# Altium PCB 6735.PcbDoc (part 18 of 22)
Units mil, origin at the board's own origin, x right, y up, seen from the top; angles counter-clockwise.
Board outline 2641.73 x 5165.35 mil, 6 copper layers (Top, Inner Layer 2, Inner Layer 3, Inner Layer 4, Inner Layer 5, Bottom), stack 35.7 mil thick; 1011 components, 790 nets, 4118 pads, 9325 vias.
Unrouted connection lines stored in the file: 4610.
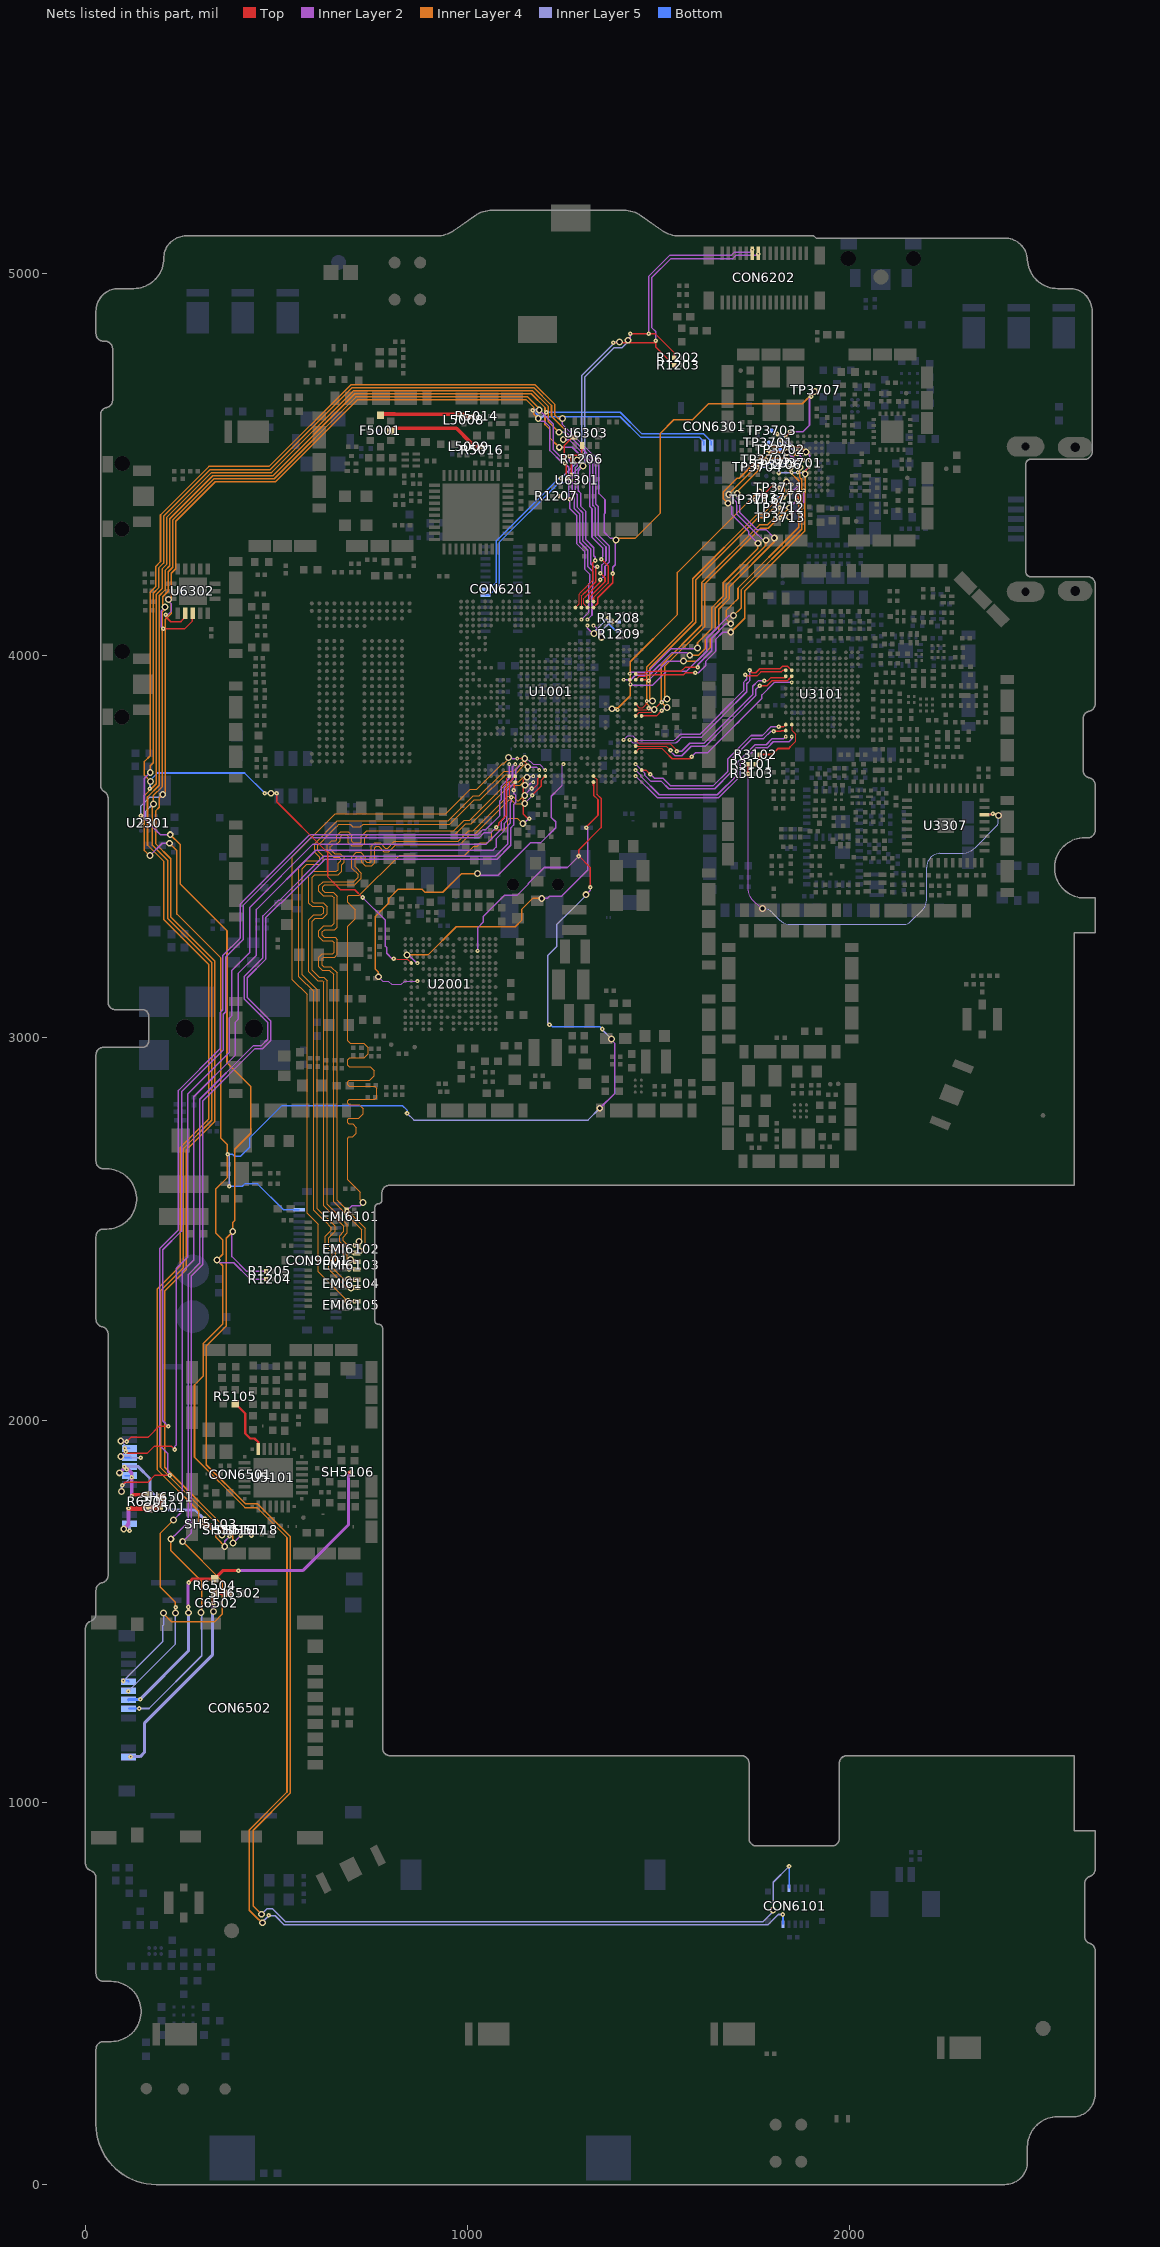
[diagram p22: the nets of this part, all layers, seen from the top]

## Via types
v1: diameter 12, hole 4, Top to Inner Layer 2, 3329 vias
v2: diameter 12, hole 4, Inner Layer 5 to Bottom, 3071 vias
v3: diameter 18, hole 10, Inner Layer 2 to Inner Layer 5, 1928 vias
v4: diameter 10, hole 4, Top to Inner Layer 2, 525 vias
v5: diameter 20, hole 12, Top to Bottom, 472 vias

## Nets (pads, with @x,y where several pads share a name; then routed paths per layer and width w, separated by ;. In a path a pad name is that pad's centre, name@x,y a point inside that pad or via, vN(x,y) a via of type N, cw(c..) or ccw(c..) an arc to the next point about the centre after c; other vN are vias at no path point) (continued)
RF_RX1_BBQP: U1001.AK6 U3101.M6 | length 513.1
  Top w3: U1001.AK6@1439.43,3748.01 1448.84,3757.43 1507.96,3757.43 1517.3,3748.09
  Top w4: 1517.3,3748.09 1535.3,3730.09 1581.31,3730.09 v1(1586.31,3735.09)
  Inner Layer 2 w4: v1(1586.31,3735.09) 1586.31,3737.09 1586.89,3737.09 1595.89,3746.09 1612.12,3746.09 1612.5,3746.48 1628.07,3746.48 1696.01,3814.41 1696.01,3814.49 1710.31,3828.78 1710.31,3829.27 1769.95,3888.91 1769.95,3895.79 1769.95,3897.21 1784.62,3911.88 1784.62,3912.2 1801.02,3928.6 1801.34,3928.6 1802.82,3930.09 v4(1847.91,3930.09)
RF_RX1_BBQP_C2K: TP3716.1 U1001.AG13 U3701.K9 | length 857.3
  Top w4: v1(1776.3,4409.11) 1776.3,4423.82 U3701.K9@1800.45,4447.97 U3701.K9@1800.57,4448.09 ; v4(1392.18,3858.25) 1393.14,3858.24 1392.3,3858.09 v4(1392.18,3858.25)
  Inner Layer 2 w4: v3(1377.44,3861.19) 1377.34,3862.05 1377.82,3861.57 1381.14,3858.24 v4(1392.18,3858.25) ; v3(1763.31,4428.09) 1763.31,4421.1 1775.8,4408.61 v1(1776.3,4409.11)
  Inner Layer 4 w4: v3(1377.44,3861.19) 1377.95,3863.83 1394.27,3863.83 1425.46,3895.02 1425.46,3984.37 1548.67,4107.58 1548.67,4217.79 1749.02,4418.15 1753.37,4418.15 v3(1763.31,4428.09)
  Inner Layer 5 w4: v2(1751.3,4408.09) 1763.31,4420.1 v3(1763.31,4428.09)
RF_RX2_BBIN: U1001.AK8 U3101.N5 | length 500.2
  Top w3: U1001.AK8@1439.43,3779.51 1449.5,3769.43 1530.23,3769.43 1547.31,3752.34 v1(1547.31,3750.09)
  Top w4: v1(1775.47,3934.13) 1784.63,3934.13 1793.37,3942.87 1829.21,3942.87 U3101.N5@1832.16,3945.83
  Inner Layer 2 w4: v1(1547.31,3750.09) 1560.22,3750.09 1581.16,3771.02 1618.68,3771.02 1672.01,3824.35 1672.01,3824.43 1686.31,3838.73 1686.31,3839.21 1745.94,3898.84 1745.94,3920.21 1759.87,3934.13 v1(1775.47,3934.13)
RF_RX2_BBIP: U1001.AK7 U3101.M5 | length 517.5
  Top w3: U1001.AK7@1439.43,3763.76 1439.42,3763.43 1519.55,3763.43 v1(1530.77,3752.21)
  Top w4: v1(1764.32,3921.61) 1783.43,3921.61 1796.69,3934.87 1837.09,3934.87 1840.17,3937.95 1840.17,3938.09 U3101.M5@1847.91,3945.83
  Inner Layer 2 w4: v1(1530.77,3752.21) 1529.5,3750.93 1542.34,3738.09 1560.12,3738.09 1584.99,3762.96 1621.93,3762.96 1680.01,3821.04 1680.01,3821.12 1694.31,3835.41 1694.31,3835.9 1753.95,3895.54 1753.95,3911.24 v1(1764.32,3921.61)
RF_RX2_BBQN: U1001.AH8 U3101.N4 | length 537.9
  Top w4: v1(1726.39,3949.77) 1726.88,3950.26 1729.93,3947.21 1756.79,3947.21 1767.28,3957.7 1820.17,3957.7 1824.05,3961.58 U3101.N4@1832.16,3961.58 ; v4(1407.93,3779.51) 1407.93,3779.71 v4(1407.93,3779.51)
  Inner Layer 2 w3: v4(1407.93,3779.51) 1419.25,3790.83 1431.56,3790.83 1443.87,3778.52 1539.75,3778.52 1542.96,3781.73 1543.93,3781.73 1545.8,3783.6
  Inner Layer 2 w4: 1545.8,3783.6 1557.29,3795.09 1608.81,3795.09 1648.01,3834.3 1648.01,3834.37 1662.31,3848.67 1662.31,3849.15 1721.83,3908.67 1721.83,3929.79 1721.94,3929.9 1721.94,3930.15 1730.39,3938.6 1730.39,3945.77 v1(1726.39,3949.77)
RF_RX2_BBQP: U1001.AJ8 U3101.M4 | length 549.4
  Top w4: v1(1738.11,3961.86) 1744.76,3955.21 1753.48,3955.21 1763.97,3965.7 1816.86,3965.7 1823.66,3972.5 1836.99,3972.5 U3101.M4@1847.91,3961.58
  Inner Layer 2 w3: v4(1423.68,3779.51) 1424,3779.82 1431.31,3772.52 1545.85,3772.52 1545.85,3773.09
  Inner Layer 2 w4: 1545.85,3773.09 1546.42,3773.66 1547.54,3773.66 1560.97,3787.09 1612.12,3787.09 1656.01,3830.98 1656.01,3831.06 1670.31,3845.35 1670.31,3845.84 1729.92,3905.45 1729.92,3926.57 ; 1729.94,3926.59 1729.94,3926.83 1738.39,3935.28 1738.39,3961.58 v1(1738.11,3961.86)
RF_TX_BBIN: U1001.AK3 U3101.N15 | length 505.3
  Top w3: v4(1439.43,3700.77) 1439.42,3700.96 v4(1439.43,3700.77)
  Top w4: U1001.AK3@1439.3,3700.76 v4(1439.43,3700.77) ; U1001.AK3@1439.3,3700.76 1439.3,3701.09 1439.75,3701.09 v4(1439.43,3700.77) ; U1001.AK3@1439.3,3700.76 v4(1439.43,3700.77)
  Inner Layer 2 w4: v4(1439.43,3700.77) 1453.31,3686.87 1453.31,3684.12 1501.34,3636.09 1653.04,3636.09 1705.65,3688.71 1705.65,3721.37 1751.45,3767.17 1780.92,3767.17 1796.37,3782.63 1826.44,3782.63 v4(1832.16,3788.35)
RF_TX_BBIN_C2K: TP3711.1 U1001.AK13 U3701.G9 | length 862.7
  Top w3: U1001.AK13@1439.43,3858.25 1439.58,3858.09 1468.31,3858.09 v1(1473.31,3863.09)
  Inner Layer 2 w4: v1(1473.31,3863.09) 1477.31,3859.09 v3(1488.31,3859.09) ; v3(1834.31,4455.09) 1840.81,4455.09 1847.81,4448.09 v4(1847.69,4447.97)
  Inner Layer 4 w4: v3(1488.31,3859.09) 1484.1,3859.09 1468.31,3874.88 1468.31,3970.48 1588.67,4090.83 1588.67,4201.23 1757.08,4369.64 1771.33,4369.64 1827.94,4426.25 1827.94,4448.72 v3(1834.31,4455.09)
  Inner Layer 5 w4: v2(1815.49,4439.1) 1816.19,4438.39 1833.59,4455.79 v3(1834.31,4455.09)
  Bottom w4: TP3711.1@1815.3,4439.09 v2(1815.49,4439.1)
RF_TX_BBIP: U1001.AK2 U3101.M15 | length 521.5
  Inner Layer 2 w4: v4(1439.43,3685.02) 1496.35,3628.09 1656.43,3628.09 1713.65,3685.31 1713.65,3718.06 1754.76,3759.17 1784.23,3759.17 1799.69,3774.63 1840.69,3774.63 1847.91,3781.85 v4(1847.91,3788.35)
RF_TX_BBIP_C2K: TP3710.1 U1001.AK14 U3701.F9 | length 841.8
  Top w3: U1001.AK14@1439.43,3873.99 1449.33,3864.09 1458.59,3864.09 1467.53,3873.03 1467.53,3881.09 v4(1468.31,3881.09)
  Inner Layer 2 w4: v4(1468.31,3881.09) v3(1483.31,3881.09) ; v3(1843.31,4429.09) 1849.3,4429.09 1864.3,4444.09 1864.3,4447.11 v4(1863.44,4447.97)
  Inner Layer 4 w4: v3(1483.31,3881.09) 1476.31,3888.09 1476.31,3967.14 1596.67,4087.49 1596.67,4197.91 1759.62,4360.87 1775.09,4360.87 v3(1843.31,4429.09)
  Inner Layer 5 w4: v2(1827.31,4413.09) 1837.3,4423.07 v3(1843.31,4429.09)
  Bottom w4: TP3710.1@1812.31,4412.09 1812.31,4412.59 1827.31,4412.59 v2(1827.31,4413.09)
RF_TX_BBQN: U1001.AK4 U3101.N14 | length 506
  Top w4: v1(1800.92,3802.63) 1800.92,3801.75 1819.01,3801.75 1821.36,3804.1 U3101.N14@1832.16,3804.1
  Inner Layer 2 w4: v4(1439.43,3716.51) 1462.95,3692.98 1462.95,3687.66 1479.53,3671.09 1507.07,3671.09 1526.07,3652.09 1646.33,3652.09 1688.29,3694.05 1688.29,3726.64 1744.82,3783.17 1756.13,3783.17 1756.19,3783.24 1774.34,3783.24 1793.72,3802.63 v1(1800.92,3802.63) v1@1801.14,3802.63
RF_TX_BBQN_C2K: TP3713.1 U1001.AK12 U3701.E10 | length 855.7
  Top w3: U1001.AK12@1439.43,3842.5 1449.01,3852.09 1480.31,3852.09 1506.31,3878.09 v1(1508.31,3878.09)
  Inner Layer 2 w4: v1(1508.31,3878.09) 1517.31,3887.09 v3(1521.31,3887.09) ; v3(1842.31,4363.09) 1878.97,4399.74 1878.97,4432.22 v4(1879.19,4432.22)
  Inner Layer 4 w4: v3(1521.31,3887.09) 1515.31,3893.09 1515.31,3971.99 1620.67,4077.34 1620.67,4187.97 1766.17,4333.47 1786.55,4333.47 1820.78,4367.7 1837.7,4367.7 v3(1842.31,4363.09)
  Inner Layer 5 w4: v2(1817.3,4361.09) 1840.31,4361.09 v3(1842.31,4363.09)
RF_TX_BBQP: U1001.AL3 U3101.N13 | length 480.3
  Top w4: U1001.AL3@1455.17,3700.77 1466.82,3700.76 v1(1477.85,3689.73) ; v1(1813.76,3813.75) 1826.07,3813.75 U3101.N13@1832.16,3819.85
  Inner Layer 2 w4: v1(1477.85,3689.73) 1488.5,3679.09 1510.96,3679.09 1529.96,3660.09 1643.01,3660.09 1680.29,3697.37 1680.29,3729.95 1741.58,3791.24 1771.02,3791.24 1794.41,3814.63 1813.76,3814.63 v1(1813.76,3813.75)
RF_TX_BBQP_C2K: TP3712.1 U1001.AL12 U3701.F10 | length 844
  Top w4: U1001.AL12@1455.17,3842.5 1493.72,3842.49 v1(1507.31,3856.09) ; v1(1860.31,4407.09) 1863.44,4410.21 U3701.F10@1863.44,4432.22
  Inner Layer 2 w4: v1(1507.31,3856.09) 1515.31,3864.09 v3(1521.31,3864.09) ; v3(1842.31,4387.09) 1841.81,4387.59 1860.81,4406.59 v1(1860.31,4407.09)
  Inner Layer 4 w4: v3(1521.31,3864.09) 1506.31,3879.09 1506.31,3974.37 1612.67,4080.73 1612.67,4191.28 1763.5,4342.12 1783.89,4342.12 1817.63,4375.86 1831.09,4375.86 v3(1842.31,4387.09)
  Inner Layer 5 w4: v2(1816.3,4387.09) v3(1842.31,4387.09)
RF_TXDET: R3101.2 R3103.1 U3307.17 | length 1256.5
  Top w5: R3101.2@1733.65,3716.09 R3103.1@1733.65,3691.09 1734.52,3691.09 v1(1734.6,3691.01) ; U3307.17@2352.03,3583.94 2352.03,3585.04 2374.38,3585.04 v1(2374.38,3586.4)
  Inner Layer 2 w3: v1(1734.6,3691.01) 1734.15,3690.57 1734.15,3385.59 ccw(c1767,3385.59) 1743.77,3362.36 1767.55,3338.59 v3(1771.65,3338.59) ; v1(2374.38,3586.4) 2377.73,3586.4 cw(c2377.73,3571.65) 2388.16,3582.08 v3(2388.65,3581.59)
  Inner Layer 5 w3: v3(1771.65,3338.59) 1772.65,3338.59 cw(c1772.65,3306.52) 1795.33,3329.2 1814.82,3309.71 ccw(c1845.28,3340.18) 1845.28,3297.09 2142.75,3297.09 ccw(c2142.75,3319.48) 2158.58,3303.65 2190.85,3335.91 ccw(c2167.17,3359.59) 2200.65,3359.59 2200.65,3446.66 cw(c2234.21,3446.66) 2210.48,3470.39 2213.51,3473.42 cw(c2235.65,3451.28) 2235.65,3482.59 2289.65,3482.59 ccw(c2289.65,3537.8) 2328.69,3498.76 2382.19,3552.26 ccw(c2366.6,3567.85) 2388.65,3567.85 v3(2388.65,3581.59)
RF_TXDET_MT6169: R3101.1 R3102.1 U3101.M13 | length 187.4
  Top w3: 1843.99,3761.25 1843.65,3761.59 1858.3,3776.24 1858.3,3781.56 1858.41,3781.67 1858.41,3793.84 1847.91,3804.34 U3101.M13@1847.91,3819.85
  Top w5: R3101.1@1753.65,3716.09 1755.67,3718.1 ccw(c1735.18,3738.59) 1764.15,3738.59 R3102.1@1764.15,3741.09 ; R3102.1@1762.66,3741.99 1763.25,3741.99 R3102.1@1764.15,3741.09 ; 1839.12,3757.06 1811.72,3757.06 1795.75,3741.09 R3102.1@1764.15,3741.09 ; 1839.16,3757.09 1839.83,3757.09 1843.99,3761.25
RF_WBT: F5001.8 L5008.1 R5014.1 | length 250.8
  Top w10: F5001.8@771.95,4629.45 771.95,4632.09 797.19,4632.09 797.31,4631.97 808.89,4631.97 ; 808.92,4631.94 809.16,4631.94 ; 809.18,4631.92 809.35,4631.92 ; 809.37,4631.9 809.53,4631.9 809.81,4631.87 809.85,4631.83 990.31,4631.83 L5008.1@990.31,4626.09 R5014.1@1014.31,4626.09
RF_WF_5G: F5001.6 L5009.1 R5016.1 | length 267.2
  Top w10: F5001.6@798.53,4588.11 805.51,4595.09 970.32,4595.09 1006.31,4559.1 1006.49,4559.1 1012.31,4553.28 L5009.1@1012.31,4547.09 ; L5009.1@1012.31,4546.09 L5009.1@1012.31,4547.09 ; R5016.1@1038.31,4547.09 L5009.1@1012.31,4547.09
RFIC1_BSI_CK: TP3703.1 U1001.AJ19 U3701.D5 | length 1121.4
  Inner Layer 2 w4: v4(1423.68,3952.73) 1427.54,3956.6 1470.4,3956.6 1531.89,4018.09 1596.31,4018.09 v3(1601.31,4020.09) ; v3(1681.31,4398.83) 1691.31,4388.83 1691.31,4368.86 1735.74,4324.43 1735.74,4317.66 v3(1759.31,4294.09) ; v3(1885.31,4533.09) 1894.94,4523.46 v4(1894.93,4510.96)
  Inner Layer 4 w4: v3(1601.31,4020.09) 1601.31,4034.12 1638.95,4071.76 1638.95,4126.3 1668.95,4156.3 1668.95,4190.92 1759.31,4281.29 v3(1759.31,4294.09) ; v3(1681.31,4398.83) 1668.22,4411.92 1668.22,4427.7 1704.61,4464.09 1710.71,4464.09 1793.71,4547.09 1871.31,4547.09 v3(1885.31,4533.09)
  Inner Layer 5 w4: v2(1810.05,4580.13) 1820.31,4580.13 1854.36,4546.09 1870.3,4546.09 v3@1879.3,4537.09
  Bottom w4: TP3703.1@1795.31,4589.09 1797.12,4590.89 1807.89,4580.13 v2(1810.05,4580.13)
RFIC1_BSI_D0: TP3702.1 U1001.AL18 U3701.E5 | length 1066.5
  Top w4: U1001.AL18@1455.17,3936.99 1473.75,3936.99 1474.55,3937.78 1474.69,3937.64 v1(1474.22,3934.97)
  Inner Layer 2 w4: v1(1474.22,3934.97) 1474.22,3936.55 1523.48,3985.81 1545.69,3985.81 1545.97,3986.09 v3(1564.31,3986.09) ; v3(1705.31,4424.09) 1705.31,4412.09 1712.31,4405.09 1712.31,4373.91 1756.13,4330.09 1780.31,4330.09 v3(1802.31,4308.09) ; v3@1868.31,4530.09 v3(1862.31,4531.09) 1879.97,4513.43 1879.97,4511.74 v4(1879.19,4510.96)
  Inner Layer 4 w4: v3(1564.31,3986.09) 1587.69,3986.09 1587.95,3985.83 1599.58,3985.83 1634.95,4021.2 1634.95,4041.89 1656.95,4063.89 1656.95,4121.67 1684.95,4149.67 1684.95,4180.58 1802.31,4297.94 v3(1802.31,4308.09) ; v3(1705.31,4424.09) 1704.78,4424.09 1704.78,4429.09 1792.78,4517.09 1848.31,4517.09 v3(1862.31,4531.09)
  Inner Layer 5 w4: v2(1820.32,4563.15) 1825.72,4563.15 1836.58,4552.29 1857.79,4531.09 v3(1862.31,4531.09)
  Bottom w4: TP3702.1@1817.31,4539.09 1817.31,4560.15 v2(1820.32,4563.15)
RFIC1_BSI_EN: TP3701.1 U1001.AH18 U3701.F5 | length 1071.9
  Inner Layer 2 w4: v4(1407.93,3936.99) 1426.71,3936.98 1438.32,3948.59 1474.95,3948.59 1533.58,4007.22 1575.05,4007.22 v3(1581.12,4001.15) ; v3(1683.22,4421.49) 1703.95,4400.76 1703.95,4370.96 1759.23,4315.68 1759.73,4315.68 1771.31,4304.09 v3(1780.31,4302.09) ; v3(1835.31,4532.09) 1847.31,4520.09 1852.1,4520.09 1862.33,4509.85 v4(1863.44,4510.96)
  Inner Layer 4 w4: v3(1581.12,4001.15) 1603.59,4001.15 1621.95,4019.51 1621.95,4042.23 1647.95,4068.23 1647.95,4123.99 1676.95,4152.99 1676.95,4185.78 1780.31,4289.15 v3(1780.31,4302.09) ; v3(1683.22,4421.49) 1682.36,4422.35 1792.1,4532.09 v3(1835.31,4532.09)
  Inner Layer 5 w4: v2(1788.31,4536.09) 1831.31,4536.09 v3(1835.31,4532.09)
  Bottom w4: v2(1788.31,4536.09) 1788.31,4546.09 TP3701.1@1788.3,4557.09
RFIC1_TX_BSI_CK: TP3706.1 U1001.AK18 U3701.E7 | length 957.5
  Top w3: U1001.AK18@1439.43,3936.99 1449.05,3946.61 1465.15,3946.61 1468.63,3950.09 1489.3,3950.09
  Top w4: 1489.3,3950.09 1565.04,3950.09 1570.11,3955.16 v1(1595.79,3955.16) ; U3701.E7@1879.19,4479.47 1879.06,4479.59 1893.43,4493.96 v4(1893.3,4494.09)
  Inner Layer 2 w4: v1(1595.79,3955.16) 1604.02,3955.16 1622.44,3973.58 1622.44,3984.83 1648.7,4011.09 1648.7,4042.69 1667.54,4061.53 v3(1688.16,4061.53) ; v3(1883.3,4475.09) 1883.3,4484.09 v4(1893.3,4494.09)
  Inner Layer 4 w4: v3(1688.16,4061.53) 1724.88,4098.25 1724.88,4169.27 1882.31,4326.71 1882.31,4425.82 1883.3,4426.81 v3(1883.3,4475.09)
  Inner Layer 5 w4: v2(1814.31,4478.09) 1880.3,4478.09 v3(1883.3,4475.09)
  Bottom w4: TP3706.1@1810.3,4500.09 1814.31,4496.07 v2(1814.31,4478.09)
RFIC1_TX_BSI_D0: TP3705.1 U1001.AJ18 U3701.F7 | length 963.8
  Top w4: U1001.AJ18@1423.68,3936.99 1424.84,3936.99 1424.84,3925.06 v4(1426,3925.06)
  Inner Layer 2 w4: v4(1426,3925.06) 1428.46,3922.61 1483.66,3922.61 1520.15,3959.09 1572.84,3959.09 1625.38,4011.63 1625.38,4045.95 1683.35,4103.92 1683.35,4104.23 1683.74,4104.62 1695.82,4104.62 v3(1695.82,4104.94) ; v4(1863.44,4479.47) 1863.44,4486.23 v3(1870.3,4493.09)
  Inner Layer 4 w4: v3(1695.82,4104.94) 1715.31,4124.43 1715.31,4172.13 1874.31,4331.13 1874.31,4461.79 1868.3,4467.81 1868.3,4479.07 1868.31,4493.09 v3(1870.3,4493.09)
  Inner Layer 5 w4: v2(1781.31,4512.09) 1781.31,4514.09 1815.27,4514.09 1820.27,4509.09 1851.41,4509.09 1867.41,4493.09 v3(1870.3,4493.09)
RFIC1_TX_BSI_EN: TP3704.1 U1001.AK19 U3701.G7 | length 942.9
  Top w3: U1001.AK19@1439.43,3952.73 1462.79,3952.73 1469.14,3959.09 1489.3,3959.09
  Top w4: 1489.3,3959.09 1558.42,3959.09 1569.57,3970.24 v1(1602.13,3970.24)
  Inner Layer 2 w4: v1(1602.13,3970.24) 1602.13,3976.48 1638.31,4012.66 1638.31,4045.77 1676.07,4083.53 v3(1688.16,4083.53) ; v3(1844.31,4494.09) 1846,4494.09 1846,4479.46 v4(1847.69,4479.47)
  Inner Layer 4 w4: v3(1688.16,4083.53) 1675.95,4095.73 1675.95,4118.04 1684.74,4126.83 1695.74,4137.83 1703.95,4146.05 1707.31,4149.41 1707.31,4176.93 1866.31,4335.93 1866.31,4457.44 1844.31,4479.44 v3(1844.31,4494.09)
  Inner Layer 5 w4: v2(1759.3,4493.09) 1780.19,4493.09 1793.19,4506.09 1808.65,4506.09 1815.65,4499.09 1839.31,4499.09 v3(1844.31,4494.09)
RTC32K1V8: U1001.AC1 U2001.P5 | length 868.4
  Top w4: v1(1309.73,3549.88) 1308.95,3550.83 1340.95,3582.83 1340.95,3623.52 1329.95,3634.52 1329.95,3658.93 1329.19,3659.69 U1001.AC1@1329.19,3669.27
  Inner Layer 2 w4: v3(841.27,3217.06) 845.61,3217.06 866.72,3195.95 v4(868.34,3195.95) ; v3(1193.95,3364.83) 1207.95,3364.83 1213.95,3370.83 1245.67,3370.83 1313.95,3439.11 1313.95,3546.58 1310.19,3550.34 v1(1309.73,3549.88)
  Inner Layer 4 w4: v3(841.27,3217.06) 896.48,3217.06 970.25,3290.83 1124.27,3290.83 1141.95,3308.52 1141.95,3337.04 1169.74,3364.83 v3(1193.95,3364.83)
RXIN_P: R5105.1 U5101.23 | length 152.7
  Top w4: R5105.1@391.29,2042.07 R5105.1@392.31,2043.09 R5105.1@393.31,2043.09
  Top w6: R5105.1@392.31,2043.09 418.31,2017.09 418.31,1965.19 431.42,1952.09 442.48,1952.09 451.93,1942.64 U5101.23@451.93,1923.99
SCL0: CON6201.23 CON6202.18 R1203.2 U1001.AA30 | length 1932.6
  Top w3: U1001.AA30@1297.69,4125.96 1297.69,4156.23 1301.95,4160.49
  Top w4: 1301.95,4160.49 1307.7,4166.23 1307.95,4166.23 1334.95,4193.23 1334.95,4227.83 1338.95,4231.83 v1(1339.15,4232.93) ; v1(1380.97,4819.21) v1@1492.24,4819.21 ; v1(1492.24,4823.66) v1@1492.24,4819.21 ; R1203.2@1540.95,4759.83 1533.54,4767.24 1533.47,4767.24 1533.31,4767.09 1532.89,4767.09 1492.24,4807.74 v1@1492.24,4819.21
  Inner Layer 2 w4: v3(1286.1,4511.66) 1286.1,4496.25 1281.31,4491.46 1281.31,4427.05 1287.31,4421.05 1287.31,4388.05 1301.3,4374.06 1301.3,4299.89 1321.94,4279.25 1321.94,4240.84 1330.95,4231.83 1338.95,4231.83 v1(1339.15,4232.93) ; v1(1380.97,4819.21) 1380.97,4819.81 1397.16,4819.81 v3(1397.16,4820.41) ; v1(1492.24,4823.66) 1492.24,4847.88 1481.31,4858.81 1481.31,4988.72 1531.69,5039.09 1693.94,5039.09 1702.94,5048.09 1757.24,5048.09 v1(1760.2,5051.05)
  Inner Layer 5 w4: v2(1244.08,4464.11) 1286.1,4506.13 v3(1286.1,4511.66) 1285.53,4512.22 1298.31,4525 1298.31,4732.83 1385.89,4820.41 v3(1397.16,4820.41)
  Bottom w4: CON6201.23@1046.63,4174.4 1046.63,4173.15 1056.15,4173.15 1074.31,4191.31 1074.31,4299.45 1238.97,4464.11 v2(1244.08,4464.11)
SCL1: CON6101.3 R1205.2 U1001.AB31 | length 7541
  Top w4: U1001.AB31@1313.44,4141.71 1319.76,4148.03 1319.76,4154.21 1359.31,4193.76 1359.31,4203.67 v1(1347.31,4215.67)
  Inner Layer 2 w4: v3(169.51,3694.09) 153.31,3677.89 153.31,3574.88 196.46,3531.73 v3(221.9,3531.73) ; v3(385.31,2493.09) 383.3,2491.08 383.3,2427.85 422.26,2388.89 v1(472.6,2388.89) ; v3(1250.03,4565.38) 1264.91,4565.38 1327.31,4502.97 1327.31,4393.52 1333.31,4387.52 1333.31,4313.15 1361.95,4284.51 1361.95,4247.99 1351.31,4237.35 1351.31,4219.67 v1(1347.31,4215.67)
  Inner Layer 4 w4: v3(169.51,3694.09) 169.51,3712.29 177.31,3720.09 177.31,4163.42 192.31,4178.42 192.31,4230.5 204.31,4242.5 204.31,4364.91 326.49,4487.09 483.72,4487.09 697.72,4701.09 1173.19,4701.09 1219.31,4654.97 1219.31,4626.71 1257.81,4588.22 1257.81,4573.15 v3(1250.03,4565.38) ; v3(221.9,3531.73) 248.31,3505.31 248.31,3402.14 370.31,3280.14 370.31,2935.09 432.31,2873.09 432.31,2750.73 390.31,2708.73 390.31,2522.09 385.31,2517.09 v3(385.31,2493.09) 368.31,2476.09 368.31,2246.04 316.31,2194.04 316.31,1883.45 418.67,1781.09 450.15,1781.09 535.95,1695.29 535.95,1024.09 438.95,927.09 438.95,728.45 v3(460.31,707.09)
  Inner Layer 5 w4: v3(460.31,707.09) 474.31,721.09 490.31,721.09 524.31,687.09 1772.31,687.09 1799.31,714.09 v3(1799.31,718.09) 1799.31,790.85 v2(1840.75,832.29)
  Bottom w4: CON6101.3@1840.75,775.18 1840.75,831.91 1840.94,832.1 v2(1840.75,832.29)
SCL2: CON6301.3 R1207.2 SH5117.1 U1001.AA28 U2301.C3 U6301.B3 U6302.2 U6303.12 | length 5570.4
  Top w4: v1(210.51,4107.42) 210.31,4102.13 223.36,4089.09 249.07,4089.09 253.72,4093.74 253.72,4094.35 261.27,4101.9 U6302.2@261.27,4110.76 ; v1(405.95,1697.49) SH5117.1@405.95,1710.49 ; R1207.2@1241.95,4417.49 1249.61,4409.83 v1(1267.31,4409.83) ; U6301.B3@1270.95,4458.49 U6301.B3@1271.2,4458.49 ; U6303.12@1277.96,4571.65 1274.52,4571.64 1252.77,4549.89 1252.77,4517.09 1257.13,4512.73 1257.13,4503.35 v1(1254.03,4503.35) 1257.13,4502.98 1258.31,4501.8 1258.31,4471.37 ; 1258.31,4471.37 U6301.B3@1271.2,4458.49 ; 1258.31,4471.37 U6301.B3@1271.2,4458.49
  Inner Layer 2 w4: v1(210.51,4107.42) 213.05,4104.87 224.81,4116.63 224.81,4135.52 217.03,4143.3 v3(217.31,4147.24) ; v3(385.95,1678.29) 386.15,1678.09 405.75,1697.69 v1(405.95,1697.49) ; v3(1184.74,4620.87) 1192.79,4612.83 1200.49,4612.83 1215.31,4598.01 1215.31,4536.85 1247.44,4504.72 1255.4,4504.72 v1(1254.03,4503.35) 1264.31,4493.06 1264.31,4412.83 v1(1267.31,4409.83) 1267.31,4385.13 1284.95,4367.49 1284.95,4293.6 1305.92,4272.64 1305.92,4226.64 1318.95,4213.6 1318.95,4189.61 1317.31,4187.97 1317.31,4114.08 v4(1297.69,4094.47)
  Inner Layer 4 w4: v3(385.95,1678.29) 385.95,1697.84 207.31,1876.48 207.31,2337.69 264.31,2394.69 264.31,2707.46 338.31,2781.46 338.31,3201.43 223.31,3316.43 223.31,3468.85 183.31,3508.85 183.31,3593.36 193.31,3603.36 193.31,3628.09 v3(202.31,3637.09) 203.31,3637.09 209.31,3643.09 209.31,4095.23 224.31,4110.23 224.31,4135.02 216.53,4142.8 217.03,4143.3 v3(217.31,4147.24) 219.14,4145.41 224.31,4150.58 224.31,4215.58 236.31,4227.58 236.31,4351.66 339.74,4455.09 497.03,4455.09 711.03,4669.09 1153.84,4669.09 1172.31,4650.62 1172.31,4633.3 v3(1184.74,4620.87)
  Inner Layer 5 w4: v2(145.26,3581.19) 145.26,3607.09 167.26,3629.09 194.31,3629.09 v3(202.31,3637.09) ; v3(1184.74,4620.87) 1188.5,4621.09 1189.68,4619.91 1207.77,4638.01 1206.92,4637.16 v2(1205.34,4637.12)
  Bottom w4: v2(1205.34,4637.12) 1399.28,4637.12 1456.31,4580.09 1617.71,4580.09 1637.24,4560.56 CON6301.3@1637.24,4550.11
SCL3: R1209.2 U1001.AB27 | length 138.4
  Inner Layer 2 w4: v4(1313.44,4078.72) 1313.44,4072 1328.45,4056.99 1328.8,4057.33 v3(1330.31,4058.09)
  Inner Layer 5 w4: v3(1330.31,4058.09) 1328.32,4060.08 1348.79,4080.56 v2(1367.31,4099.09)
  Bottom w4: v2(1367.31,4099.09) 1367.31,4085.12 1385.94,4066.49 R1209.2@1395.95,4066.49
SDA0: CON6201.22 CON6202.20 R1202.2 U1001.Y30 | length 1903.4
  Top w3: U1001.Y30@1281.94,4125.96 1291.36,4135.38 1291.36,4161.39 1295.46,4165.49
  Top w4: 1295.46,4165.49 1308.13,4178.16 1308.57,4178.16 1326.95,4196.55 1326.95,4242.09 v1(1333.95,4249.09) ; v1(1425.11,4842.05) 1425.88,4842.83 v1(1473.95,4842.83) 1490.04,4842.83 1540.95,4791.92 R1202.2@1540.95,4779.83 ; CON6202.20@1744.46,5053.06 CON6202.20@1744.46,5053.06 ; v1(1744.71,5062.09) 1744.45,5062.09 CON6202.20@1744.45,5054.95 ; CON6202.20@1744.31,5055.09 CON6202.20@1744.45,5054.95 ; CON6202.20@1744.31,5055.09 1744.38,5053.05 1744.45,5051.05 CON6202.20@1744.46,5053.06 ; CON6202.20@1744.31,5055.09 CON6202.20@1744.46,5053.06 ; CON6202.20@1744.46,5053.06 CON6202.20@1744.45,5054.95
  Inner Layer 2 w4: v3(1301.67,4496.09) 1289.31,4483.73 1289.31,4431.57 1295.31,4425.57 1295.31,4391.45 1309.3,4377.46 1309.3,4303.21 1329.95,4282.57 1329.95,4261.48 1333.95,4257.47 v1(1333.95,4249.09) ; v3(1419.64,4825.45) 1419.64,4826.42 1425.11,4831.88 v1(1425.11,4842.05) ; v1(1473.95,4842.83) 1473.95,4852.84 1473.31,4853.48 1473.31,4992.03 1529.37,5048.09 1690.35,5048.09 1698.35,5056.09 1738.71,5056.09 v1(1744.71,5062.09)
  Inner Layer 5 w4: v2(1262.08,4463.11) 1295.06,4496.09 v3(1301.67,4496.09) 1306.31,4500.73 1306.31,4729.51 1382.15,4805.35 1403.32,4805.35 1419.64,4821.68 v3(1419.64,4825.45)
  Bottom w4: CON6201.22@1046.63,4158.65 1046.63,4157.76 1055.79,4157.76 1082.31,4184.27 1082.31,4296.14 1238.27,4452.09 1251.06,4452.09 v2(1262.08,4463.11)
SDA1: CON6101.2 R1204.2 U1001.AB30 | length 7467.7
  Top w3: 1307.46,4153.49 1304.02,4150.05 1304.02,4135.38 1308.31,4131.09 U1001.AB30@1313.44,4125.96
  Top w4: 1307.46,4153.49 1346.95,4192.98 v1(1346.95,4198.83)
  Inner Layer 2 w4: v3(168.57,3477.03) 200.76,3509.21 v3(219.96,3509.21) v3@221.9,3507.38 ; v3(344.31,2419.09) 351.91,2411.49 387.91,2411.49 430.51,2368.89 v1(472.6,2368.89) ; v3(1239.09,4584.52) 1257.08,4584.52 1335.31,4506.29 1335.31,4396.85 1341.31,4390.85 1341.31,4316.46 1369.95,4287.82 1369.95,4244.55 1359.31,4233.91 1359.31,4210.7 1353.56,4204.95 1353.07,4204.95 v1(1346.95,4198.83)
  Inner Layer 4 w4: v3(168.57,3477.03) 167.97,3476.43 154.31,3490.09 154.31,3633.94 185.31,3664.94 185.31,4160.09 200.31,4175.09 200.31,4226.83 212.31,4238.83 212.31,4361.6 329.8,4479.09 487.04,4479.09 701.04,4693.09 1169.87,4693.09 1211.31,4651.65 1211.31,4612.3 v3(1239.09,4584.52) ; v3(219.96,3509.21) 239.31,3489.86 239.31,3323.86 354.31,3208.86 354.31,2737.58 371.31,2720.58 371.31,2635.09 340.31,2604.09 340.31,2490.4 359.31,2471.4 359.31,2434.09 v3(344.31,2419.09) 359.31,2404.09 359.31,2251.19 308.31,2200.19 308.31,2115.09 285.31,2092.09 285.31,1903.14 417.36,1771.09 448.84,1771.09 527.31,1692.61 527.31,1026.83 428.31,927.83 428.31,717.88 453.48,692.7 453.93,692.7 454.09,692.87 455.53,692.87 v3(463.31,685.09)
  Inner Layer 5 w4: v3(463.31,685.09) 462.31,686.09 v2@479.31,703.09 ; v2(1823.95,706.49) 1812.44,706.49 1785.04,679.09 520.31,679.09 496.31,703.09 v2@479.31,703.09 ; v2@479.31,703.09 v2(479.31,705.09) 480.31,704.09 v2@479.31,703.09
  Bottom w4: v2(1823.95,706.49) 1825,705.43 CON6101.2@1825.01,680.7
SDA2: CON6301.2 R1206.2 SH5118.1 U1001.AB28 U2301.C2 U6301.C3 U6302.3 U6303.2 | length 5560.6
  Top w4: v1(203.31,4070.09) 259.21,4070.09 279.95,4090.83 279.95,4109.76 U6302.3@280.95,4110.76 ; v1(434.31,1697.09) 434.07,1696.85 434.14,1696.78 435.95,1698.59 SH5118.1@435.95,1710.49 ; U6301.C3@1271.2,4474.24 1271.2,4516.62 v1(1265.84,4521.98) 1268.35,4524.49 R1206.2@1297.95,4524.49 1297.95,4547.34 U6303.2@1299.95,4549.34 ; U6303.2@1299.95,4549.34 1299.95,4549.49 U6303.2@1300.11,4549.5 ; U6303.2@1299.95,4549.34 U6303.2@1300.11,4549.5 ; U6303.2@1299.95,4549.34 U6303.2@1300.11,4549.5
  Inner Layer 2 w4: v1(203.31,4070.09) 198.31,4075.09 198.31,4116.88 v3(208.51,4127.07) ; v3(357.55,1699.78) 367.6,1709.83 421.57,1709.83 v1(434.31,1697.09) ; v3(1187.31,4643.12) 1223.31,4607.12 1223.31,4540.16 1241.49,4521.98 v1(1265.84,4521.98) 1265.84,4508.36 1273.31,4500.89 1273.31,4422.4 1279.31,4416.4 1279.31,4384.62 1292.95,4370.98 1292.95,4296.92 1313.94,4275.94 1313.94,4233.73 1326.95,4220.72 1326.95,4176.03 1325.31,4174.39 1325.31,4106.33 v4(1313.44,4094.47)
  Inner Layer 4 w4: v3(357.55,1699.78) 357.55,1714.93 196.31,1876.17 196.31,2338.38 256.31,2398.38 256.31,2710.79 330.31,2784.79 330.31,3197.45 215.31,3312.45 215.31,3464.28 175.31,3504.28 175.31,3610.04 v3(177.64,3612.37) 177.64,3634.03 201.31,3657.7 201.31,4114.39 208.49,4121.57 v3(208.51,4127.07) 208.49,4125.55 201.95,4132.09 201.95,4154.09 216.31,4168.45 216.31,4219.5 228.31,4231.5 228.31,4354.97 336.43,4463.09 493.7,4463.09 707.7,4677.09 1157.15,4677.09 1187.31,4646.93 v3(1187.31,4643.12)
  Inner Layer 5 w4: v2(145.26,3561.5) 157.31,3573.55 157.31,3592.04 v3(177.64,3612.37) ; v2(1169.93,4642.6) 1170.46,4643.12 v3(1187.31,4643.12)
  Bottom w4: v2(1169.93,4642.6) 1187.45,4625.08 1399.47,4625.08 1452.46,4572.09 1606.03,4572.09 1617.56,4560.56 CON6301.2@1617.56,4550.11
SDA3: R1208.2 U1001.AC27 | length 112.4
  Inner Layer 2 w4: v4(1329.19,4078.72) 1330.35,4078.71 1350.31,4058.75 v3(1350.31,4048.09)
  Inner Layer 5 w4: v3(1350.31,4048.09) 1350.31,4065.3 1374.1,4089.09 v2(1380.31,4089.09)
  Bottom w4: v2(1380.31,4089.09) 1394.95,4089.09 R1208.2@1394.95,4088.49
SIM1_NFC_SWP1: CON6501.6 R6501.2 SH5103.1 | length 517.2
  Top w8: v1(307.31,1724.09) 308.31,1725.09 SH5103.1@329.31,1725.09
  Top w10: v1(121.31,1801.09) 125.06,1804.83 R6501.2@164.95,1804.83
  Inner Layer 2 w4: v1(107.95,1871.83) v1@107.95,1875.09
  Inner Layer 2 w8: v3(89.31,1862.09) 100.02,1872.79 v1@103.95,1872.79 ; v1(307.31,1724.09) 309.78,1724.09 309.78,1739.02 v3(312.24,1739.02)
  Inner Layer 2 w9: v1@103.95,1872.79 106.24,1875.09 107.95,1875.09 109.58,1873.46 121.31,1861.72 v1(121.31,1801.09)
  Inner Layer 5 w8: v3(89.31,1862.09) 101.31,1874.09 v2(101.31,1878.09) 138.31,1878.09 168.95,1847.45 168.95,1815.03 219.15,1764.83 286.43,1764.83 v3(312.24,1739.02)
  Bottom w4: v2(101.31,1878.09) 115.3,1878.09 CON6501.6@115.3,1878.55
SIM1_SCLK: CON6501.3 U1001.K4 | length 2696.1
  Top w4: v1(104.95,1917.83) 109.95,1912.83 162.22,1912.83 162.22,1913.81 180.5,1932.09 224.31,1932.09 v1(233.31,1923.09)
  Inner Layer 2 w4: v3(92.31,1905.09) v1@104.98,1917.8 ; v1(233.31,1923.09) 233.31,1931.09 237.31,1935.09 237.31,2396.38 267.31,2426.38 267.31,2852.66 376.31,2961.66 376.31,3051.69 383.31,3058.69 383.31,3177.05 430.31,3224.05 430.31,3341.79 595.61,3507.09 1047.97,3507.09 1067.97,3527.09 1068.28,3527.09 1087.31,3546.12 1087.31,3566.38 1095.31,3574.38 1095.31,3653.17 1117.31,3675.17 1117.31,3709.36 v4(1124.46,3716.51)
  Inner Layer 5 w4: v3(92.31,1905.09) 118.33,1905.09 121.93,1901.49 v2(144.95,1901.49)
  Bottom w4: CON6501.3@115.3,1902.17 103.39,1902.17 115.3,1901.98 v2(144.95,1901.49)
SIM1_SIO: CON6501.7 U1001.J2 | length 2528.2
  Top w3: 1100.95,3649.49 1100.95,3653.71 1102.47,3655.22 1102.47,3678.77 U1001.J2@1108.72,3685.02
  Top w4: v1(107.89,1943.99) 118.99,1955.09 164.58,1955.09 164.58,1956.07 192.83,1984.32 v1(216.07,1984.32) ; v1(1075.31,3551.09) 1081.31,3557.09 1081.31,3562.23 1100.95,3581.86 1100.95,3649.49
  Inner Layer 2 w4: v3(92.31,1945.09) 94.69,1945.09 95.95,1943.83 107.73,1943.83 v1(107.89,1943.99) ; v1(216.07,1984.32) 202.31,1998.08 202.31,2445.51 251.31,2494.51 251.31,2859.3 360.31,2968.3 360.31,3061.65 367.31,3068.65 367.31,3211.91 413.31,3257.91 413.31,3347.42 588.99,3523.09 1029.52,3523.09 1043.52,3537.09 1061.31,3537.09 v1(1075.31,3551.09)
  Inner Layer 5 w4: v3(92.31,1945.09) 102.31,1935.09 v2(102.31,1926.09)
  Bottom w4: v2(102.31,1926.09) 115,1926.09 CON6501.7@115.3,1925.79
SIM1_SRST: CON6501.2 U1001.J4 | length 2750.2
  Top w4: v1(96.31,1830.09) 103.06,1836.83 162.82,1836.83 ; 163.22,1836.83 162.82,1836.83 ; v1(220.31,1856.09) 182.08,1856.09 162.82,1836.83
  Inner Layer 2 w4: v3(94.31,1813.09) 94.31,1814.09 96.31,1816.09 v1(96.31,1830.09) ; v1(220.31,1856.09) 220.31,1860.09 215.31,1865.09 215.31,1912.74 194.31,1933.74 194.31,2448.93 243.31,2497.93 243.31,2862.62 352.31,2971.62 352.31,3066.55 359.31,3073.55 359.31,3215.58 405.31,3261.58 405.31,3350.73 585.67,3531.09 1025.83,3531.09 1039.83,3545.09 1047.57,3545.09 1084.31,3581.83 1084.31,3620.39 1088.31,3624.39 1088.31,3659 1108.71,3679.4 v4(1108.72,3716.51)
  Inner Layer 5 w4: v3(94.31,1813.09) 94.31,1825.09 119.45,1850.23 v2(121.55,1850.23)
  Bottom w4: v2(121.55,1850.23) 115.33,1850.24 CON6501.2@115.3,1854.92 ; CON6501.2@115.3,1854.92 103.15,1854.92 CON6501.2@115.3,1854.92
SIM1_VCC: C6501.1 CON6501.1 R6501.1 SH6501.2 | length 235.7
  Top w12: v1(112.68,1769.09) 112.95,1768.83 R6501.1@164.95,1768.83 164.95,1770.83 C6501.1@196.95,1770.83 196.95,1797.83 SH6501.2@197.95,1797.83
  Inner Layer 2 w10: v3(100.31,1715.09) 112.68,1727.45 v1(112.68,1769.09)
  Inner Layer 5 w8: v3(100.31,1715.09) 99.16,1716.24 109.66,1726.74 115.31,1721.09 v2(115.31,1711.09)
  Bottom w4: v2(115.31,1711.09) 115.31,1721.88 111.78,1725.45 108.31,1728.94 CON6501.1@115.3,1728.94
SIM2_NFC_SWP2: CON6502.6 R6504.2 SH5106.1 | length 1018.7
  Top w8: v1(270.31,1575.09) 280.06,1584.83 R6504.2@337.95,1584.83 359.21,1606.09 v1(400.31,1606.09) ; SH5106.1@689.95,1863.49 690.55,1864.09 v1(696.31,1864.09)
  Inner Layer 2 w8: v3(269.31,1496.09) v1(269.31,1511.09) 268.31,1512.09 268.31,1573.09 v1(270.31,1575.09) ; v1(400.31,1606.09) 568.31,1606.09 688.31,1726.09 688.31,1856.09 v1(696.31,1864.09)
  Inner Layer 5 w8: v2(142.95,1269.49) 269.31,1395.85 v3(269.31,1496.09)
  Bottom w8: CON6502.6@113.14,1268.24 113.14,1269.49 v2(142.95,1269.49)
SIM2_SCLK: CON6502.3 U1001.L4 | length 3175.6
  Top w4: v1(236.31,1510.09) 235.91,1510.09 236.11,1509.89 v1@237.31,1508.68
  Inner Layer 2 w4: v3(230.31,1738.47) 253.31,1761.47 253.31,2388.72 283.31,2418.72 283.31,2846.03 392.31,2955.03 392.31,3041.53 399.31,3048.53 399.31,3168.39 447.31,3216.39 447.31,3336.16 602.24,3491.09 1066.05,3491.09 1074.31,3499.36 1074.31,3520.59 1096.31,3542.59 1096.31,3561.25 1102.31,3567.25 1102.31,3647.34 1126.31,3671.34 1126.31,3702.61 v4(1140.21,3716.51) ; v3(235.31,1495.09) 235.31,1510.09 v1(236.31,1510.09)
  Inner Layer 4 w4: v3(230.31,1738.47) 195.31,1703.47 195.31,1563.78 235.31,1523.78 v3(235.31,1495.09)
  Inner Layer 5 w4: v2(112.31,1291.09) 235.31,1414.09 v3(235.31,1495.09)
  Bottom w4: v2(112.31,1291.09) CON6502.3@113.14,1291.86 CON6502.3@113.14,1291.86
SIM2_SIO: CON6502.7 U1001.K1 | length 3326.5
  Top w4: v1(1120.95,3647.49) 1121.95,3646.49 1121.95,3666.75 U1001.K1@1124.46,3669.27
  Inner Layer 2 w4: v3(254.31,1682.09) 277.31,1705.09 277.31,2377.67 307.31,2407.67 307.31,2835.67 443.73,2972.09 463.63,2972.09 484.75,2993.21 484.75,3044.4 423.31,3105.83 423.31,3157.27 472.31,3206.27 472.31,3315.72 508.38,3351.78 510.74,3351.78 626.05,3467.09 1075.99,3467.09 1112.89,3503.99 1112.89,3549.56 1120.13,3556.8 1120.13,3610.26 1126.19,3616.32 1126.19,3634.19 1120.95,3639.43 v1(1120.95,3647.49)
  Inner Layer 4 w4: v3(204.31,1495.09) 203.53,1494.31 225.76,1472.09 337.31,1472.09 357.31,1492.09 357.31,1579.09 v3(254.31,1682.09)
  Inner Layer 5 w4: v2(98.95,1317.49) 202.31,1420.85 202.31,1462.09 204.31,1464.09 v3(204.31,1495.09)
  Bottom w4: v2(98.95,1317.49) 113.14,1317.49 CON6502.7@113.14,1315.48 ; CON6502.7@113.14,1315.48 112.71,1315.48 112.31,1315.09 112.31,1314.65 CON6502.7@113.14,1315.48
SIM2_SRST: CON6502.2 U1001.K2 | length 3294.2
  Top w3: v1(1114.19,3629.16) 1109.45,3633.9 1109.45,3670 U1001.K2@1124.46,3685.02
  Inner Layer 2 w4: v3(223.32,1689.09) 231.94,1697.71 233.15,1697.71 269.31,1733.88 269.31,2381.25 299.31,2411.25 299.31,2839.4 440,2980.09 460.31,2980.09 476.75,2996.52 476.75,3040.28 415.31,3101.71 415.31,3160.7 464.31,3209.7 464.31,3319.13 498.34,3353.15 498.43,3353.15 505.06,3359.78 507.43,3359.78 622.74,3475.09 1072.67,3475.09 1104.82,3507.24 1104.82,3555.63 1111.31,3562.12 1111.31,3615.45 1114.19,3618.33 v1(1114.19,3629.16)
  Inner Layer 4 w4: v3(223.32,1689.09) 223.32,1659.09 304.31,1578.09 304.31,1496.29 v3(302.13,1496.29)
  Inner Layer 5 w4: v2(140.95,1245.49) 166.31,1245.49 304.31,1383.49 304.31,1496.09 v3(302.13,1496.29)
  Bottom w4: CON6502.2@113.14,1244.61 113.14,1245.49 v2(140.95,1245.49)
SIM2_VCC: C6502.1 CON6502.1 R6504.1 SH6502.2 | length 585.6
  Top w8: v1(333.95,1520.83) 333.95,1548.83 R6504.1@337.95,1548.83 337.95,1547.09 SH6502.2@374.31,1547.09
  Inner Layer 2 w8: v1(333.95,1520.83) 333.95,1503.83 331.32,1501.2 333.7,1498.82 v3(334.96,1499.13)
  Inner Layer 5 w8: v2(117.95,1119.49) 142.95,1119.49 154.95,1131.49 154.95,1208.09 331.95,1385.09 331.95,1497.83 333.7,1498.82 v3(334.96,1499.13)
  Bottom w4: CON6502.1@113.14,1118.63 114,1119.49 v2(117.95,1119.49)
SRCLKENA0: U1001.V4 U2001.P8 | length 1044.2
  Inner Layer 2 w3: v3(766.31,3160.09) 778.31,3148.09 792.73,3148.09 800.73,3140.09 826.62,3140.09 835.23,3148.7 v4(868.34,3148.7) ; 1237.95,3651.49 1247.45,3660.99 1247.45,3713.52 v4(1250.45,3716.51)
  Inner Layer 2 w4: v3(1025.86,3429.77) 1029.93,3425.7 1079.42,3425.7 1164.91,3511.18 1191.62,3511.18 1230.31,3549.88 1230.31,3565.29 1218.95,3576.65 1218.95,3632.49 1237.95,3651.49
  Inner Layer 4 w4: v3(766.31,3160.09) 766.31,3172.09 757.95,3180.45 757.95,3317.55 793.95,3353.55 793.95,3364.94 817.84,3388.83 880.58,3388.83 888.32,3381.09 934.88,3381.09 983.56,3429.77 v3(1025.86,3429.77)
SRCLKENA1: TP3707.1 U1001.AC30 U2001.R5 U3701.H1 | length 4594.9
  Top w3: v1(806.63,3207.37) 813.36,3207.37 815.36,3205.37 843.17,3205.37 843.85,3204.7 848.22,3200.32 U2001.R5@852.59,3195.95
  Top w4: v1(500.99,3640.1) 500.72,3639.84 500.72,3618.02 633.31,3485.43 633.31,3422.09 667.57,3387.83 704.78,3387.83 v1(725.17,3367.44) ; U1001.AC30@1329.19,4125.96 1340.31,4137.09 1340.31,4151.49 1379.39,4190.57 1379.39,4209.77 v1(1379.34,4215.02) ; U3701.H1@1831.94,4573.96 1833.08,4575.09 1834.31,4575.09 1842.31,4583.09 v1(1842.31,4586.09) ; v1(1898.31,4678.09) 1910.31,4690.09 TP3707.1@1910.31,4694.09
  Inner Layer 2 w4: v3(485.67,3640.09) v1(500.99,3640.1) ; v1(725.17,3367.44) 784.31,3308.29 784.31,3240.09 788.09,3236.31 788.09,3221.34 802.06,3207.37 v1(806.63,3207.37) ; v3(1247.86,4620.58) 1247.86,4605.06 1343.31,4509.61 1343.31,4424.4 1359.31,4408.4 1359.31,4372.24 1357.31,4370.24 1357.31,4323.09 1372.57,4307.83 v3@1384.95,4307.83 ; v1(1379.34,4215.02) 1379.34,4231.12 1386.31,4238.09 v3@1386.31,4304.66 ; v3(1387.98,4302.85) v3@1386.31,4304.66 ; v1(1842.31,4586.09) 1877.63,4586.09 1894.31,4602.77 1894.31,4674.09 v1(1898.31,4678.09) 1897.31,4679.09 1908.31,4690.09 v3(1907.31,4691.09) ; v3@1384.95,4307.83 1386.31,4306.47 v3@1386.31,4304.66 ; v3@1384.95,4307.83 1384.31,4307.19 1384.31,4306.83 v3@1386.31,4304.66
  Inner Layer 4 w4: v3(170.06,3671.22) 154.31,3686.96 154.31,3723.26 169.31,3738.26 169.31,4166.75 184.31,4181.75 184.31,4234.18 196.31,4246.18 196.31,4368.23 323.18,4495.09 480.4,4495.09 694.4,4709.09 1176.5,4709.09 1227.31,4658.28 1227.31,4630.13 1236.86,4620.58 v3(1247.86,4620.58) ; v3(1387.98,4302.85) 1387.98,4306.83 1437.46,4306.83 1504.31,4373.69 1504.31,4582.06 1539.34,4617.09 1588.35,4617.09 1630.35,4659.09 1875.31,4659.09 v3(1907.31,4691.09)
  Inner Layer 5 w4: v2(168.59,3651.95) 168.59,3670.33 v3(170.06,3671.22) ; v2(468.95,3640.49) 468.95,3640.29 485.67,3640.29 v3(485.67,3640.09)
  Bottom w4: v2(168.59,3651.95) 169.99,3651.95 169.99,3674.88 188.21,3693.09 416.35,3693.09 v2(468.95,3640.49)
SRCLKENAI: SH5116.1 U1001.AC31 | length 4711.7
  Top w4: SH5116.1@375.95,1710.49 375.95,1696.83 v1(376.95,1695.83) ; U1001.AC31@1329.19,4141.71 1329.19,4152.01 1367.31,4190.13 1367.31,4235.07 v1(1349.6,4252.78)
  Inner Layer 2 w4: v3(364.48,1669.04) 364.48,1683.36 v1(376.95,1695.83) ; v3(1239.52,4545.16) 1273.81,4545.16 1319.31,4499.66 1319.31,4390.2 1325.31,4384.2 1325.31,4309.83 1353.95,4281.19 1353.95,4259.74 1348.3,4254.08 v1(1349.6,4252.78)
  Inner Layer 4 w4: v3(364.48,1669.04) 355.72,1677.81 355.72,1679.37 340.31,1694.77 340.31,1703.3 322.52,1721.09 308.96,1721.09 296.31,1733.74 296.31,1761.75 188.31,1869.75 188.31,2343.97 248.31,2403.97 248.31,2714.12 322.31,2788.12 322.31,3192.14 205.31,3309.14 205.31,3461.64 162.31,3504.64 162.31,3630.32 193.31,3661.32 193.31,4156.77 208.31,4171.77 208.31,4223.16 220.31,4235.16 220.31,4358.29 333.12,4471.09 490.37,4471.09 704.37,4685.09 1166.56,4685.09 1202.31,4649.34 1202.31,4604.84 1215.31,4591.84 1215.31,4569.37 v3(1239.52,4545.16)
SYSRSTB: CON9001.4 U1001.AC2 U2001.D3 | length 2954.3
  Top w3: U1001.AC2@1329.19,3685.02 1338.61,3675.59 1338.61,3651.98 ; 1338.57,3651.94 1338.61,3651.98 ; 1338.61,3637.17 1338.61,3651.98
  Top w4: v1(1320.81,3393.93) 1320.81,3445.97 v1(1290.95,3475.83) 1290.95,3492.47 1348.95,3550.47 1348.95,3626.83 1338.61,3637.17 1338.3,3637.48
  Inner Layer 2 w4: v4(1025.82,3227.44) 1025.82,3287.9 1040.95,3303.04 1040.95,3317.83 1095.95,3372.83 1129.24,3372.83 1157.95,3401.54 1157.95,3403.36 1200.42,3445.83 1260.95,3445.83 v1(1290.95,3475.83) ; v3(1309.24,3374.77) 1309.24,3375.12 1311.95,3377.83 1312.71,3377.83 1320.81,3385.93 v1(1320.81,3393.93) ; v3(1345.72,2815.83) 1385.31,2855.42 1385.31,2985.71 1375.15,2995.87 v3(1376.46,2997.18)
  Inner Layer 5 w4: v2(371.94,2695.52) 376.31,2691.15 376.31,2623.53 376.19,2623.41 v2(376.19,2612.04) ; v2(841.31,2803.09) 859.31,2785.09 1314.98,2785.09 v3(1345.72,2815.83) ; v2(1214.07,3034.67) 1209.31,3039.43 1209.31,3215.37 1233.31,3239.37 1233.31,3297.01 1309.24,3372.94 v3(1309.24,3374.77) ; v2(1352.31,3023.32) 1352.31,3021.33 v3(1376.46,2997.18)
  Bottom w4: v2(371.94,2695.52) 384.89,2695.52 390.31,2690.09 405.66,2690.09 429.31,2713.74 429.31,2738.4 513,2822.09 830.31,2822.09 841.31,2811.09 v2(841.31,2803.09) ; v2(376.19,2612.04) 410.26,2612.04 416.31,2618.09 450.11,2618.09 517.25,2550.95 CON9001.4@559.07,2550.95 ; v2(1214.07,3034.67) 1215.09,3035.69 1221.69,3029.09 1346.54,3029.09 v2(1352.31,3023.32) ; CON9001.4@547.04,2550.94 CON9001.4@559.07,2550.94 ; CON9001.4@547.04,2550.94 CON9001.4@559.07,2550.95 ; CON9001.4@547.04,2550.94 547.94,2550.05 CON9001.4@559.07,2550.05 ; CON9001.4@559.07,2550.05 CON9001.4@559.07,2550.95 ; CON9001.4@559.07,2550.05 CON9001.4@559.07,2550.94
TCN: EMI6103.1 U1001.N1 | length 1991.1
  Top w4: v1(707.31,2415.09) EMI6103.1@710.07,2414.93
  Inner Layer 2 w4: v3(693.08,2420.11) 693.08,2419.09 686.3,2419.09 686.3,2418.09 707.31,2418.09 v1(707.31,2415.09) ; v3(1150.3,3661.09) 1150.3,3662.09 1160.58,3662.09 1162.98,3664.49 1163.7,3664.49 1168.48,3669.27 v4(1171.71,3669.27)
  Inner Layer 4 w3: 644.07,3503.34 641.08,3500.35 641.08,3493.89 652.86,3482.11 667.08,3482.11 677.08,3472.11 677.08,3459.55 670.08,3452.55 670.08,3436.11 661.08,3427.11 600.15,3427.11 593.58,3420.53 593.58,3356.35 596.82,3353.11 621.81,3353.11 632.08,3342.84 632.08,3324.38 620.81,3313.11 601.36,3313.11 593.58,3305.33 593.58,3177.33 611.82,3159.09 623.31,3159.09 632.31,3150.09 632.31,2564.47 685.3,2511.48 685.3,2489.83 674.08,2478.61 674.08,2469.86 685.3,2458.64 685.3,2418.26 686.47,2417.09 693.08,2417.09 v3(693.08,2420.11) ; 644.09,3503.34 647.86,3507.11 652.82,3507.11 ; 652.84,3507.09 657.79,3507.09 666.08,3515.38 666.08,3525.35 671.72,3530.98 684.21,3530.98 688.08,3527.09 688.08,3510.36 696.33,3502.11 723.31,3502.11 731.08,3509.88 731.08,3524.11 739.56,3532.59 966.88,3532.59 994.38,3560.09 1009.05,3560.09 1018.17,3569.21 1110.05,3661.09 1137.04,3661.09 1144.04,3668.09 1146.31,3668.09 1150.3,3664.1 v3(1150.3,3661.09)
TCP: EMI6103.4 U1001.N2 | length 2007.5
  Top w3: v1(707.31,2395.09) EMI6103.4@710.07,2395.25
  Inner Layer 2 w4: v3(690.08,2398.11) 690.08,2396.09 706.31,2396.09 v1(707.31,2395.09) ; v3(1155.3,3682.09) 1155.3,3683.55 1171.71,3683.55 v4(1171.71,3685.02)
  Inner Layer 4 w3: v3(690.08,2398.11) 688.68,2396.71 676.3,2409.09 676.3,2454.91 665.08,2466.13 665.08,2482.34 676.3,2493.56 676.3,2507.68 623.31,2560.67 623.31,3146.36 619.58,3150.09 607.82,3150.09 584.58,3173.33 584.58,3309.06 597.63,3322.11 617.08,3322.11 623.08,3328.11 623.08,3339.11 618.08,3344.11 593.08,3344.11 584.58,3352.61 584.58,3424.26 596.42,3436.11 656.57,3436.11 661.08,3440.61 661.08,3456.81 668.08,3463.81 668.08,3468.38 663.35,3473.11 649.11,3473.11 632.08,3490.14 632.08,3504.08 644.11,3516.11 654.08,3516.11 657.08,3519.11 657.08,3529.08 667.99,3539.98 687.93,3539.98 697.08,3530.84 697.08,3514.09 700.06,3511.11 719.31,3511.11 722.08,3513.88 722.08,3527.84 735.83,3541.59 963.15,3541.59 990.65,3569.09 1005.32,3569.09 1106.32,3670.09 1133.31,3670.09 1145.31,3682.09 v3(1155.3,3682.09) v3@1154.3,3681.09
TDN0: EMI6102.1 U1001.P2 | length 1988.9
  Top w4: v1(704.3,2456.09) 705.14,2456.93 EMI6102.1@710.07,2456.93 ; v1@1169.29,3651.14 v1(1167.95,3652.49) 1170.61,3651.14 1183.95,3664.49 1183.95,3679.61 1188.4,3684.06 U1001.P2@1187.46,3685.02
  Inner Layer 2 w4: v1(704.3,2456.09) v3(715.3,2467.09) ; v3(1149.3,3634.09) 1151.29,3638.49 1166.61,3653.82 v1(1167.95,3652.49)
  Inner Layer 4 w3: v3(715.3,2467.09) 711.31,2463.1 712.3,2463.1 715.31,2460.09 716.78,2460.09 722.8,2466.11 722.8,2498.21 649.31,2571.7 649.31,3166.11 638.33,3177.09 620.09,3177.09 610.58,3186.6 610.58,3211.59 619.1,3220.11 646.91,3220.11 650.3,3223.5 650.3,3249.11 645.3,3254.11 621.35,3254.11 610.58,3264.88 610.58,3280.33 623.35,3293.11 643.82,3293.11 650.3,3299.59 650.3,3366.83 645.02,3372.11 622.35,3372.11 610.83,3383.63 610.83,3397.86 622.08,3409.11 701.35,3409.11 713.08,3420.83 713.08,3427.6 696.3,3444.38 696.3,3473.05 708.35,3485.11 719.81,3485.11 732.08,3472.83 732.08,3463.11 736.08,3459.11 745.08,3459.11 748.08,3462.11 748.08,3500.83 757.35,3510.11 770.81,3510.11 784.81,3496.11 790.42,3496.11 808.42,3514.11 840.06,3514.11 ; 840.08,3514.09 975.08,3514.09 1003.08,3542.09 1015.09,3542.09 1105.11,3632.11 1118.08,3632.11 1129.08,3621.11 1133.99,3621.11 1146.97,3634.09 v3(1149.3,3634.09)
TDN1: EMI6104.1 U1001.P3 | length 1986.7
  Top w3: EMI6104.1@710.07,2366.93 710.28,2367.15 v1(714.24,2367.15)
  Top w4: EMI6104.1@709.91,2367.09 EMI6104.1@710.07,2366.93 EMI6104.1@709.91,2367.09
  Inner Layer 2 w4: v3(688.6,2368.09) 689.54,2367.15 v1(714.24,2367.15) ; v3(1157.3,3709.6) 1157.3,3709.09 1158.95,3708.49 1179.73,3708.49 v4@1187.45,3700.76
  Inner Layer 4 w3: 617.31,3480.86 622.31,3475.86 622.31,3462 614.4,3454.09 578.52,3454.09 567.58,3443.15 567.58,3164.88 606.31,3126.15 606.31,2553.61 653.08,2506.84 653.08,2494.38 636.31,2477.61 636.31,2458.44 639.67,2455.09 648.04,2455.09 655.31,2447.82 655.31,2418.36 645.31,2408.36 645.31,2398.09 679.31,2364.09 687.6,2364.09 688.6,2365.09 v3(688.6,2368.09) ; 617.31,3480.87 608.31,3489.87 608.31,3504.34 620.31,3516.34 630.31,3526.34 638.31,3534.35 644.31,3540.35 649.31,3545.35 653.31,3549.35 656.31,3552.35 658.31,3554.35 663.05,3559.09 692.87,3559.09 699.86,3552.1 719.3,3552.1 726.29,3559.09 952.99,3559.09 1016.99,3623.09 1033.33,3623.09 1099.33,3689.09 1123.31,3689.09 1148.31,3714.09 1157.3,3714.09 v3(1157.3,3709.6)
  other v4: 1187.46,3700.77
TDN2: EMI6105.1 U1001.M3 | length 2023
  Top w3: v4(1129.5,3730.65) 1129.89,3730.51 1130.95,3730.51 1130.95,3731.49 1140.93,3731.49 1155.96,3716.46 U1001.M3@1155.96,3700.77
  Top w4: v1(703.93,2311.15) 710.07,2311.15 EMI6105.1@710.07,2310.93
  Inner Layer 2 w4: v3(687.08,2310.11) 687.08,2310.63 703.93,2310.63 v1(703.93,2311.15) ; v3(1106.95,3733.49) 1109.95,3733.49 1110.31,3734.48 1112.95,3734.49 1116.95,3730.49 1129.89,3730.49 v4(1129.5,3730.65)
  Inner Layer 4 w3: v3(1106.95,3733.49) 1106.95,3730.48 1094.03,3717.56 1090.26,3717.56 1023.77,3651.07 1023.77,3650.83 1007.15,3650.83 942.87,3586.55 653.74,3586.55 541.58,3474.39 541.58,3152.78 580.3,3114.05 580.3,2541.21 608.66,2512.85 608.66,2388.53 679.27,2317.92 679.27,2310.13 v3@684.31,2305.09 ; v3@684.31,2305.09 684.31,2307.34 v3@686.22,2309.25 ; v3@684.31,2305.09 686.22,2303.18 v3@686.22,2308.55 ; v3@684.31,2305.09 v3@686.22,2308.55 ; v3@686.22,2308.55 v3@686.22,2309.25 ; v3@686.22,2308.55 v3(687.08,2310.11) v3@686.22,2309.25
TDN3: EMI6101.1 U1001.M2 | length 2050.8
  Top w4: EMI6101.1@684.11,2546.59 684.11,2547.9 v1(684.3,2548.09) ; U1001.M2@1155.96,3685.02 1145.95,3675.01 1145.95,3628.49 1144.95,3627.49 1144.95,3586.75 1159.96,3571.74 v1(1161.3,3573.09)
  Inner Layer 2 w4: v1(684.3,2548.09) 697.3,2561.09 718.3,2561.09 v3(726.3,2569.09) ; v3(1144.3,3561.09) 1145.55,3559.84 1160.05,3574.34 v1(1161.3,3573.09)
  Inner Layer 4 w3: v3(726.3,2569.09) 718.8,2576.59 718.8,2596.09 686.3,2628.59 686.3,2738.11 689.3,2741.11 698.95,2741.11 708.95,2751.1 708.95,2765.56 699.4,2775.11 689.08,2775.11 686.3,2777.89 686.3,2787.11 689.3,2790.11 715.08,2790.11 727.08,2802.11 727.08,2814.83 716.81,2825.11 690.08,2825.11 686.3,2828.89 686.3,2835.11 690.3,2839.11 757.23,2839.11 761.95,2843.83 761.95,2868.83 756.67,2874.11 690.08,2874.11 686.3,2877.89 686.3,2885.11 690.3,2889.11 744.23,2889.11 755.95,2900.83 755.95,2913.83 745.67,2924.11 690.81,2924.11 686.3,2928.61 686.3,2943.09 691.3,2948.09 729.04,2948.09 739.31,2958.36 739.31,2974.81 728.04,2986.09 693.3,2986.09 686.3,2993.09 686.3,3292.35 706.08,3312.13 706.08,3335.11 685.8,3355.39 685.8,3370.11 688.8,3373.11 716.91,3373.11 821.91,3478.11 992.08,3478.11 1016.06,3502.09 1024.59,3502.09 1032.59,3510.09 1053.03,3510.09 1063.3,3520.36 1063.3,3540.8 1067.59,3545.09 1096.03,3545.09 1104.3,3553.36 1104.3,3569.49 1109.3,3574.49 1129.57,3574.49 1143.63,3560.42 v3(1144.3,3561.09)
TDP0: EMI6102.4 U1001.R2 | length 2009.9
  Top w4: v1(700.47,2437.67) 709.3,2438.09 EMI6102.4@710.07,2437.25 EMI6102.4@710.07,2437.25 ; v1(1168.95,3634.83) 1168.95,3635.49 1191.95,3658.49 1191.95,3673.76 U1001.R2@1203.2,3685.02
  Inner Layer 2 w4: v1(700.47,2437.67) 700.89,2438.09 713.3,2438.09 v3(717.3,2442.09) ; v3(1149.3,3613.09) 1148.78,3613.61 1169.47,3634.31 v1(1168.95,3634.83)
  Inner Layer 4 w3: v3(717.3,2442.09) 731.8,2456.59 731.8,2502.15 658.31,2575.64 658.31,3169.84 642.04,3186.11 623.81,3186.11 619.58,3190.33 619.58,3207.86 622.83,3211.11 652.08,3211.11 659.3,3218.33 659.3,3257.45 653.64,3263.11 625.08,3263.11 620.08,3268.11 620.08,3277.11 626.08,3283.11 652.3,3283.11 659.3,3290.11 659.3,3370.56 648.75,3381.11 626.08,3381.11 621.08,3386.11 621.08,3395.11 626.08,3400.11 705.08,3400.11 722.08,3417.11 722.08,3431.33 705.3,3448.11 705.3,3469.33 711.08,3475.11 717.08,3475.11 723.08,3469.11 723.08,3459.38 732.35,3450.11 748.81,3450.11 757.08,3458.38 757.08,3497.11 761.08,3501.11 767.08,3501.11 781.08,3487.11 794.14,3487.11 812.12,3505.09 979.08,3505.09 1006.08,3532.09 1017.82,3532.09 1108.84,3623.11 1114.08,3623.11 1125.08,3612.11 1148.32,3612.11 v3(1149.3,3613.09)
TDP1: EMI6104.4 U1001.R3 | length 2032
  Top w3: v4(1203.2,3700.77) 1203.09,3700.89 1203.2,3700.99 v4(1203.2,3700.77)
  Top w4: EMI6104.4@710.07,2347.25 712.14,2347.24 v1(712.3,2347.09)
  Inner Layer 2 w3: v3(1149.43,3730.81) 1155.19,3730.81 1161.9,3724.1 1163.31,3724.1 1171.42,3715.99 1182.84,3715.99 1183.34,3715.49 1188.48,3715.49 v4(1203.2,3700.77)
  Inner Layer 2 w4: v3(695.08,2346.09) 695.08,2346.59 712.3,2346.59 v1(712.3,2347.09)
  Inner Layer 4 w3: v3(695.08,2346.09) 684.58,2346.09 636.31,2394.36 636.31,2412.09 646.31,2422.09 646.31,2443.71 643.93,2446.09 635.67,2446.09 627.31,2454.45 627.31,2481.34 643.31,2497.34 643.31,2503.89 625.53,2521.67 625.31,2521.67 597.31,2549.67 597.31,3121.92 558.58,3160.65 558.58,3446.88 575.24,3463.54 611.12,3463.54 613.31,3465.73 613.31,3472.13 599.31,3486.13 599.31,3508.08 659.32,3568.09 949,3568.09 1014,3633.09 1030.6,3633.09 1095.6,3698.09 1119.58,3698.09 1149.43,3727.94 v3(1149.43,3730.81)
